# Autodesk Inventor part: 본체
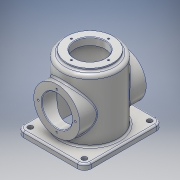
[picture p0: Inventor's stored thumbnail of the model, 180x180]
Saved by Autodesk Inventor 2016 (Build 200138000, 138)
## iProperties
Created: 2021-02
Part Number: 본체
Material: 알루미늄 6061
Document SubType Name: Modeling
Designer: user
Density: 2.7 g/cm^3
Appearance: 알루미늄 - 평지
Mass: 1235.48 g
Surface Area: 1067.61 cm^2
Volume: 457.584 cm^3
Author: user
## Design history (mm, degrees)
sketch "스케치1"
  geometry: L1 (-70, -60)-(70, -60); L2 (70, -60)-(70, 60); L3 (70, 60)-(-70, 60); L4 (-70, 60)-(-70, -60); L5 (-70, -60)-(70, 60); L6 (70, -60)-(-70, 60); 1 further point
  constraints: 12 end point, 2 midpoint, 2 parallel, 1 horizontal, 1 perpendicular
  dimensions: "d0" = 140 distance of L3.end L2.end; "d1" = 120 distance of L2.end L1.end
extrude "돌출1" new body sketch "스케치1" distance "d2" = 10; taper "d3" = 0 deg
fillet "모깎기1" dims "d4" = 12
sketch "스케치2"
  geometry: C1 r 50 at (0, 0); 1 further point
  constraints: 1 centre point, 1 coincident
  dimensions: "d5" = 100 diameter of C1
extrude "돌출2" join sketch "스케치2" distance "d6" = 110; taper "d7" = 0 deg
hole "구멍1" diameter "d10" = 9; stored, may be unused: countersink angle "d14" = 90 deg, drill point angle "d16" = 118 deg; dims "d8" = 10, "d9" = 10, "d11" = 6, "d12" = 4, "d13" = 2, "d15" = 8
node "작업 평면1"
sketch "스케치3"
  geometry: C1 r 41 at (0, 0); 1 further point
  constraints: 1 centre point, 1 coincident
  dimensions: "d24" = 82 diameter of C1
extrude "돌출3" join sketch "스케치3" stored distance "d25" = 110; taper "d26" = 0 deg
node "작업 평면2"
sketch "스케치4"
  geometry: L1 (-48, 0)-(48, 0) reference; C1 r 41 at (0, 60); 2 further points
  constraints: 1 centre point, 1 midpoint, 1 vertical alignment
  dimensions: "d28" = 82 diameter of C1; "d29" = 60 distance from line of L1 C1.centre
extrude "돌출4" join sketch "스케치4" stored distance "d30" = 110; taper "d31" = 0 deg
hole "구멍2" diameter "d34" = 54; stored, may be unused: countersink angle "d38" = 90 deg, drill point angle "d40" = 118 deg; dims "d32" = 10, "d33" = 10, "d35" = 6, "d36" = 4, "d37" = 2, "d39" = 8
sketch "스케치5"
  geometry: C1 r 42 at (0, 0); 1 further point
  constraints: 1 centre point, 1 coincident
  dimensions: "d41" = 84 diameter of C1
hole "구멍3" sketch "스케치5" at (0, 0) diameter "d42" = 84; stored, may be unused: countersink angle "d46" = 90 deg, drill point angle "d48" = 0 deg; dims "d43" = 6, "d44" = 4, "d45" = 2, "d47" = 112
hole "구멍4" diameter "d51" = 54; stored, may be unused: countersink angle "d55" = 90 deg, drill point angle "d57" = 0 deg; dims "d49" = 10, "d50" = 10, "d52" = 6, "d53" = 4, "d54" = 2, "d56" = 13
sketch "스케치6" dims "d58" = 66
  geometry: 3 further points
  constraints: 2 vertical alignment, 1 coincident, 2 other
hole "구멍5" sketch "스케치6" at (0, 33) diameter "d59" = 3.242; stored, may be unused: countersink angle "d63" = 90 deg, drill point angle "d65" = 118 deg; dims "d60" = 8, "d61" = 4, "d62" = 2, "d64" = 10
sketch "스케치7" dims "d69" = 66
  geometry: L1 (-60, 48)-(-60, -48) reference; 5 further points
  constraints: 3 horizontal alignment, 2 midpoint, 2 other
  dimensions: "d70" = 60 distance from line of L1 point (0, 0)
hole "구멍6" sketch "스케치7" at (33, 0) diameter "d71" = 3.242; stored, may be unused: countersink angle "d75" = 90 deg, drill point angle "d77" = 118 deg; dims "d72" = 8, "d73" = 4, "d74" = 2, "d76" = 10
fillet "모깎기2" dims "d81" = 3
fillet "모깎기3" dims "d82" = 3
fillet "모깎기4" dims "d83" = 6
fillet "모깎기5" dims "d84" = 3
chamfer "모따기1" distance "d85" = 1; stored, may be unused: second distance "d86" = 2, angle "d87" = 45 deg
chamfer "모따기2" distance "d88" = 1; stored, may be unused: second distance "d89" = 2, angle "d90" = 45 deg
fillet "모깎기6" dims "d91" = 3
node "작업 평면4"
sketch "스케치9"
  geometry: L1 (-58, 0)-(58, 0) reference; 3 further points
  constraints: 1 midpoint, 1 vertical alignment, 1 other
  dimensions: "d94" = 66 distance from line of L1 point (0, 66)
feature "엠보싱1" sketch "스케치9" dims "d0" = 140, "d1" = 120, "d95" = 0.5, "d96" = 0
node "솔리드1"
pattern_linear "직사각형 패턴1" dims "d19" = 116, "d22" = 96
mirror "대칭1"
pattern_circular "원형 패턴1" dims angle "d67" = 360 deg
pattern_circular "원형 패턴2" dims angle "d79" = 360 deg
mirror "대칭2"
other parameters: "d23" = -125, "d27" = 59, "d93" = 97.75
